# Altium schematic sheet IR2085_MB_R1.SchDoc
size C; SheetNumber: 0; SheetTotal: 0; PageSetup: Record=PageOptions|CenterHorizontal=True|CenterVertical=True|PrintScale=0.54|XCorrection=1.00|YCorrection=1.00|PrintKind=1|BorderSize=5000000|LeftOffset=0|BottomOffset=0|Orientation=2|PaperLength=1000|PaperWidth=1000|Scale=100|PaperSource=15|PrintQuality=600|MediaType=1|DitherType=10|PaperKind=Letter|PrintScaleMode=1
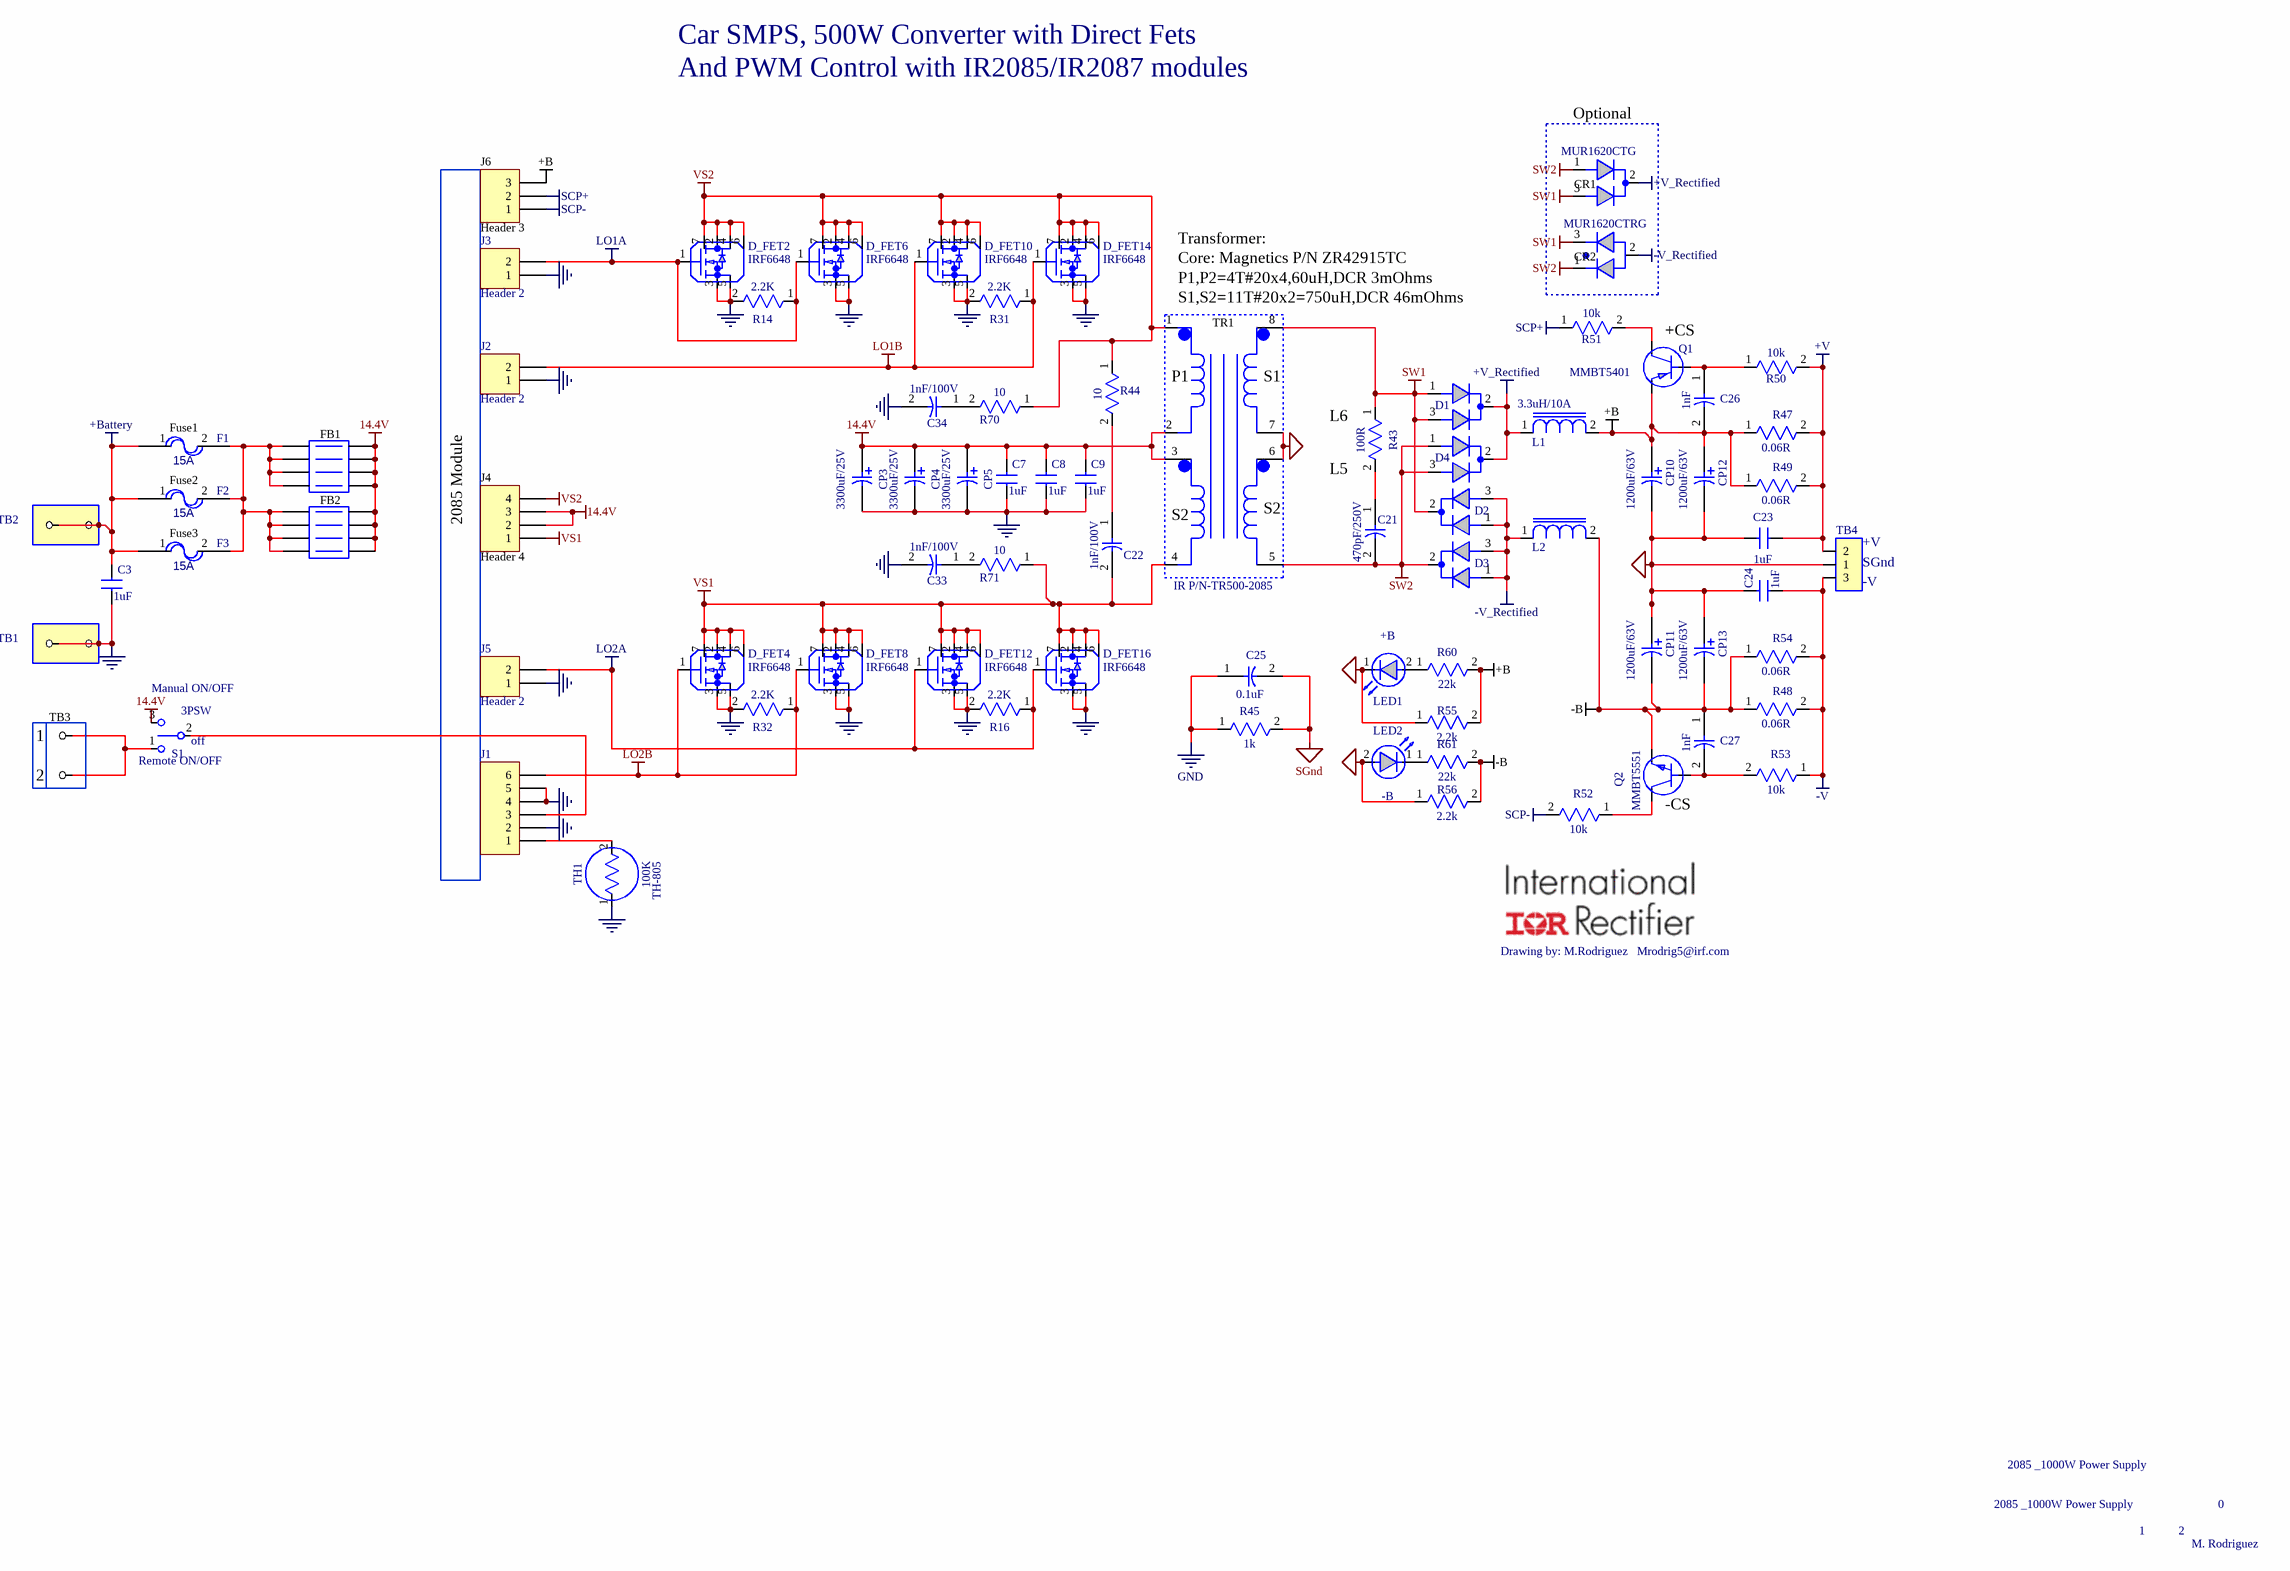
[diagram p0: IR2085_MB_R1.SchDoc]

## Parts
C3  1uF  [C-1206]
C7  1uF  [C-1206]
C8  1uF  [C-1206]
C9  1uF  [C-1206]
C21  value 470pF/250V  [C-1206]  (hidden comment: C-1206)
C22  value 1nF/100V  [C-1206]  (hidden comment: C-1206)
C23  1uF  [1812]
C24  1uF  [1812]
C25  value 0.1uF  [C-1206]  (hidden comment: C-1206)
C26  value 1nF  [C-603]  (hidden comment: C-603)
C27  value 1nF  [C-603]  (hidden comment: C-603)
C33  value 1nF/100V  [C-1206]  (hidden comment: C-1206)
C34  value 1nF/100V  [C-1206]  (hidden comment: C-1206)
CP3  value 3300uF/25V  [CP7.5MMX18D]  (hidden comment: CP7.5MMX16D)
CP4  value 3300uF/25V  [CP7.5MMX18D]  (hidden comment: CP7.5MMX16D)
CP5  value 3300uF/25V  [CP7.5MMX18D]  (hidden comment: CP7.5MMX16D)
CP10  value 1200uF/63V  [CP7.5MMX18D]  (hidden comment: CP7.5MMX18DX31H)
CP11  value 1200uF/63V  [CP7.5MMX18D]  (hidden comment: CP7.5MMX18DX31H)
CP12  value 1200uF/63V  [CP7.5MMX18D]  (hidden comment: CP7.5MMX18DX31H)
CP13  value 1200uF/63V  [CP7.5MMX18D]  (hidden comment: CP7.5MMX18DX31H)
CR1  value MUR1620CTG  [TO220+RECT_BOT]  (hidden comment: TO220+RECT)
CR2  value MUR1620CTRG  [TO220+RECT_BOT]  (hidden comment: TO220-RECT)
D1  Dual Diode  [DPAK (TO-252)]  (value not drawn)
D2  Dual Diode  [DPAK (TO-252)]  (value not drawn)
D3  Dual Diode  [DPAK (TO-252)]  (value not drawn)
D4  Dual Diode  [DPAK (TO-252)]  (value not drawn)
D_FET2  IRF6648  [IRF6648]
D_FET4  IRF6648  [IRF6648]
D_FET6  IRF6648  [IRF6648]
D_FET8  IRF6648  [IRF6648]
D_FET10  IRF6648  [IRF6648]
D_FET12  IRF6648  [IRF6648]
D_FET14  IRF6648  [IRF6648]
D_FET16  IRF6648  [IRF6648]
F1  20A  [FUSE-F065-ND_FUSE-F065-ND(Primary)]  (value not drawn)
F2  20A  [FUSE-F065-ND_FUSE-F065-ND(Primary)]  (value not drawn)
F3  20A  [FUSE-F065-ND_FUSE-F065-ND(Primary)]  (value not drawn)
FB1  FB  [FB300x4]  (value not drawn)
FB2  FB  [FB300x4]  (value not drawn)
Fuse1  value 15A  (hidden comment: FUSE-F065-ND)
Fuse2  value 15A  (hidden comment: FUSE-F065-ND)
Fuse3  value 15A  (hidden comment: FUSE-F065-ND)
J1  Header 6H  [HDR1X6]  (value not drawn)
J2  Header 2  [HDR1X2]
J3  Header 2  [HDR1X2]
J4  Header 4  [HDR1X4]
J5  Header 2  [HDR1X2]
J6  Header 3  [HDR1X3]
L1  value 3.3uH/10A  [L-513-1522-ND]  (hidden comment: 3.3uH)
L2  3.3uH  [L-513-1522-ND]  (value not drawn)
LED1  +B  [LED-805]
LED2  -B  [LED-805]
Q1  value MMBT5401  [SOT23-PNP]  (hidden comment: SOT23-PNP)
Q2  value MMBT5551  [SOT23-NPN_SOT23-NPN(Primary)]  (hidden comment: SOT23-NPN)
R14  value 2.2K  [R-805]  (hidden comment: R-805)
R16  value 2.2K  [R-805]  (hidden comment: R-805)
R31  value 2.2K  [R-805]  (hidden comment: R-805)
R32  value 2.2K  [R-805]  (hidden comment: R-805)
R43  value 100R  [R-1206]  (hidden comment: R-1206)
R44  value 10  [R-1206]  (hidden comment: R-1206)
R45  value 1k  [R-1206]  (hidden comment: R-1206)
R47  value 0.06R  [R-2512]  (hidden comment: R-2512)
R48  value 0.06R  [R-2512]  (hidden comment: R-2512)
R49  value 0.06R  [R-2512]  (hidden comment: R-2512)
R50  value 10k  [R-603]  (hidden comment: R-603)
R51  value 10k  [R-603]  (hidden comment: R-603)
R52  value 10k  [R-603]  (hidden comment: R-603)
R53  value 10k  [R-603]  (hidden comment: R-603)
R54  value 0.06R  [R-2512]  (hidden comment: R-2512)
R55  value 2.2k  [R-2512]  (hidden comment: R-2512)
R56  value 2.2k  [R-2512]  (hidden comment: R-2512)
R60  value 22k  [R-1206]  (hidden comment: R-1206)
R61  value 22k  [R-1206]  (hidden comment: R-1206)
R70  value 10  [R-1206]  (hidden comment: R-1206)
R71  value 10  [R-1206]  (hidden comment: R-1206)
S1  3PSW  [S1]
TB1  TB  [TB-Gold]  (value not drawn)
TB2  TB  [TB-Gold]  (value not drawn)
TB3  277-1022-ND  [TB_277_1022_ND_Remote On/Off()]  (value not drawn)
TB4  277-1272  [J HEADER3]  (value not drawn)
TH1  TH-805  value 100K  [TH-805]
TR1  value IR P/N-TR500-2085  [TR1300]  (hidden comment: TR100)

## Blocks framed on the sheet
Optional: CR1 CR2

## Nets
14.4V: C7.1 C8.1 C9.1 CP3.1 CP4.1 CP5.1 FB1.5 FB1.6 FB1.7 FB1.8 FB2.5 FB2.6 FB2.7 FB2.8 J4.2 J4.3 S1.3 TR1.2 TR1.3
+B: C26.2 CP10.1 CP12.1 J6.3 L1.2 Q1.2(E) R47.1 R49.1 R55.2 R60.2
+Battery: C3.1 F1.1 F2.1 F3.1 TB2.1 TB2.2
+V: C23.1 R47.2 R49.2 R50.2 TB4.2
+V_Rectified: CR1.2 D1.2 D4.2 L1.1
-B: C27.1 CP11.2 CP13.2 L2.2 Q2.E R48.1 R54.1 R56.2 R61.2
-V: C24.2 R48.2 R53.1 R54.2 TB4.3
-V_Rectified: CR2.2 D2.1 D2.3 D3.1 D3.3 L2.1
GND: C3.2 C7.2 C8.2 C9.2 C25.1 C33.2 C34.2 CP3.2 CP4.2 CP5.2 D_FET2.3 D_FET2.5 D_FET4.3 D_FET4.5 D_FET6.3 D_FET6.5 D_FET8.3 D_FET8.5 D_FET10.3 D_FET10.5 D_FET12.3 D_FET12.5 D_FET14.3 D_FET14.5 D_FET16.3 D_FET16.5 J1.2 J1.4 J1.5 J2.1 J3.1 J5.1 R14.2 R16.2 R31.2 R32.2 R45.1 TB1.1 TB1.2 TH1.1
LO1A: D_FET2.1 D_FET6.1 J3.2 R14.1
LO1B: D_FET10.1 D_FET14.1 J2.2 R31.1
LO2A: D_FET12.1 D_FET16.1 J5.2 R16.1
LO2B: D_FET4.1 D_FET8.1 J1.6 R32.1
SCP+: J6.2 R51.1
SCP-: J6.1 R52.2
SGnd: C23.2 C24.1 C25.2 CP10.2 CP11.1 CP12.2 CP13.1 LED1.1(K) LED2.2(A) R45.2 R55.1 R56.1 TB4.1 TR1.6 TR1.7
SW1: CR1.3 CR2.3 D1.1 D1.3 D2.2 R43.1 TR1.8
SW2: C21.2 CR1.1 CR2.1 D3.2 D4.1 D4.3 TR1.5
VS1: C22.2 D_FET4.2 D_FET4.4 D_FET4.6 D_FET4.7 D_FET8.2 D_FET8.4 D_FET8.6 D_FET8.7 D_FET12.2 D_FET12.4 D_FET12.6 D_FET12.7 D_FET16.2 D_FET16.4 D_FET16.6 D_FET16.7 J4.1 R71.1 TR1.4
VS2: D_FET2.2 D_FET2.4 D_FET2.6 D_FET2.7 D_FET6.2 D_FET6.4 D_FET6.6 D_FET6.7 D_FET10.2 D_FET10.4 D_FET10.6 D_FET10.7 D_FET14.2 D_FET14.4 D_FET14.6 D_FET14.7 J4.4 R44.1 R70.1 TR1.1
NetC21_1: C21.1 R43.2
NetC22_1: C22.1 R44.2
NetC26_1: C26.1 Q1.1(B) R50.1
NetC27_2: C27.2 Q2.B R53.2
NetC33_1: C33.1 R71.2
NetC34_1: C34.1 R70.2
NetF1_2: F1.2 F2.2 F3.2 FB1.1 FB1.2 FB1.3 FB1.4 FB2.1 FB2.2 FB2.3 FB2.4
NetJ1_1: J1.1 TH1.2
NetJ1_3: J1.3 S1.2
NetLED1_2: LED1.2(A) R60.1
NetLED2_1: LED2.1(K) R61.1
NetQ1_3: Q1.3(C) R51.2
NetQ2_C: Q2.C R52.1
NetS1_1: S1.1 TB3.1 TB3.2

Not connected (* = marked no-connect by the designer): Fuse1 1 2; Fuse2 1 2; Fuse3 1 2

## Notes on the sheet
- Car SMPS, 500W Converter with Direct Fets
- And PWM Control with IR2085/IR2087 modules
- Transformer:
- (near TR1) P1,P2=4T#20x4,60uH,DCR 3mOhms
- Core: Magnetics P/N ZR42915TC
- (near TR1) S1,S2=11T#20x2=750uH,DCR 46mOhms
- (near Q1) +CS
- (near TR1) P1
- (near TR1) S1
- (near R43) L6
- (near R43) L5
- 2085 Module
- (near TR1) S2
- (near TB4) +V
- (near TB4) SGnd
- (near TB4) -V
- (near S1) Manual ON/OFF
- (near S1) off
- (near S1) Remote ON/OFF
- (near Q2) -CS
- Drawing by: M.Rodriguez   Mrodrig5@irf.com
- 2085 _1000W Power Supply
- 1
- 2
- M. Rodriguez
- 0

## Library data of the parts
C3 C7-C9 = CAP: CAP CER 1UF 50V X7R 1206; Vendor: Murata Electronics North America; Value: 1uF/50V; Cost 1000: 0.07410
C21 = C-1206: CAP CERM 470PF 10% 100V NP0 1206; Vendor: AVX Corporation; Cost 1000: 0.09620
C22 C33 C34 = C-1206: CAP 1000PF 100V CERAMIC X7R 1206; Vendor: Kemet; Cost 1000: 0.04420
C23 C24 = CAP: CAP 1.0UF 100V CERAMIC X7R 1812; Vendor: Panasonic - ECG; Value: 1uF/100V
C25 = C-1206: CAP CER .1UF 50V 10% X7R 1206; Vendor: Murata Electronics North America
C26 C27 = C-603: CAP CERM 1000PF 10% 50V NP0 0603; Vendor: AVX Corporation
CP3-CP5 = CP7.5MMX16D: CAP 3300UF 25V ELECT PW RADIAL; Vendor: Nichicon
CP10-CP13 = CP7.5MMX16D: CAP 1200UF 63V ELECT PW RADIAL; Vendor: Nichicon
CR1 = TO220+RECT: (Optional) DIODE Comm Cathode ULT FAST 16A 200V TO220AB; Type: DIODE ULT FAST 16A 200V TO220AB; Vendor: ON Semiconductor; Cost 1000: 0.40470
CR2 = TO220-RECT: (Optional) DIODE Comm  Anode ULT FAST 16A 200V TO220AB; Type: DIODE ULT FAST 16A 200V TO220AB; Cost 1000: 0.50732; Vendor: ON Semiconductor
D1 D4 = Dual Diode: DIODE FAST 200V 10A D-PAK; Value: STTH1002CB; Vendor: STMicroelectronics
D2 D3 = Dual Diode: DIODE ULT FAST 200V DPAK; Value: FFD10UP20S; Vendor: Fairchild Semiconductor
D_FET2 D_FET4 D_FET6 D_FET8 D_FET10 D_FET12 D_FET14 D_FET16 = IRF6648: Direct-FET MOSFET N-CH 60V 86A; Vendor: International Rectifier; Cost 1000: 1.6400
F1-F3 = FUSE2: FUSEHOLDR MINI VERT PCB MNT SNGL; Vendor: Littelfuse Inc; Value: Fuse Holder; Fuse: F993-ND; Fuse Type: FUSE BLADE 20A/32V MINI FAST-ACT
FB1 FB2 = FB300x4: FERRITE 3 LINE 10A 342 OHMS; Value: FERRITE QUAD LINE 10A 342 OHMS; Vendor: Stwart
Fuse1-Fuse3 = FUSE-F065-ND: FUSE BLADE 15A/32V MINI FAST-ACT; Vendor: Littelfuse Inc; Cost 1000: 0.29725
J1 = Header 6H: Control Module; Value: Module_2085_R2; Vendor: IR Module_2085_R2 PCB Assy
J2 J3 J5 = Header 2: Control Module
J4 = Header 4: Control Module
J6 = Header 3: Control Module
L1 = L-513-1522-ND: INDUCTOR POWER 3.31UH 11.4A T/H
L2 = L-513-1522-ND: INDUCTOR POWER 3.31UH 11.4A T/H; Value: 3.3uH/10A
LED1 LED2 = LED-805: LED 468NM BLUE CLEAR 0805 SMD; Vendor: Lite-On Inc; Cost 1000: 0.20000
Q1 = SOT23-PNP: TRANSISTOR PNP 150V SOT-23; Vendor: Fairchild Semiconductor
Q2 = SOT23-NPN: TRANSISTOR NPN 160V SOT-23; Vendor: Fairchild Semiconductor
R14 R16 R31 R32 = R-805: RES 2.2K OHM 1/8W 5% 0805 SMD; Vendor: Rohm
R43 = R-805: RES 100 OHM 1/4W 5% 1206 SMD; Vendor: Yageo
R44 R70 R71 = R-805: RES 10 OHM 1/4W 5% 1206 SMD; Vendor: Rohm; Cost 1000: 0.01929
R45 = R-805: RES 1.0K OHM 1/4W 5% 1206 SMD; Vendor: Rohm; Cost 1000: 0.01929
R47-R49 R54 = R-2512: RES .06 OHM 1W 1% 2512 SMD; Vendor: Vishay/Dale
R50-R53 = R-603: RES 10K OHM 1/10W 5% 0603 SMD; Vendor: Rohm; Cost 1000: 0.01462
R55 R56 = R-2512: RES 2.2K OHM 1W 5% 2512 SMD; Vendor: Panasonic - ECG; Cost 1000: 0.19140
R60 R61 = R-805: RES 22K OHM 1/4W 5% 1206 SMD; Vendor: Rohm; Cost 1000: 0.01929
S1 = 3PSW: Toggle SW 3Pos; Vendor: E-Switch; Cost 1000: 1.38475
TB1 TB2 = TB-8 AWG: Gold terminal Block #8 AWG; Audio Express P/N: 070-850; Vendor: Audio Express
TB3 = 277-1022-ND: CONN TERM BLOCK 2POS 5MM PCB; Value: TB 2 terminals; Vendor: Phoenix Contact
TB4 = CONN3: CONN TERM BLOCK 3POS 9.52MM PCB; Value: 1714984; Vendor: Phoenix Contact
TH1 = TH-805: THERMISTOR 100K OHM NTC 0805 SMD; Vendor: Murata Electronics North America
TR1 = TR100: Power Transformer; Vendor: Custom P/N IR-TR500-2085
